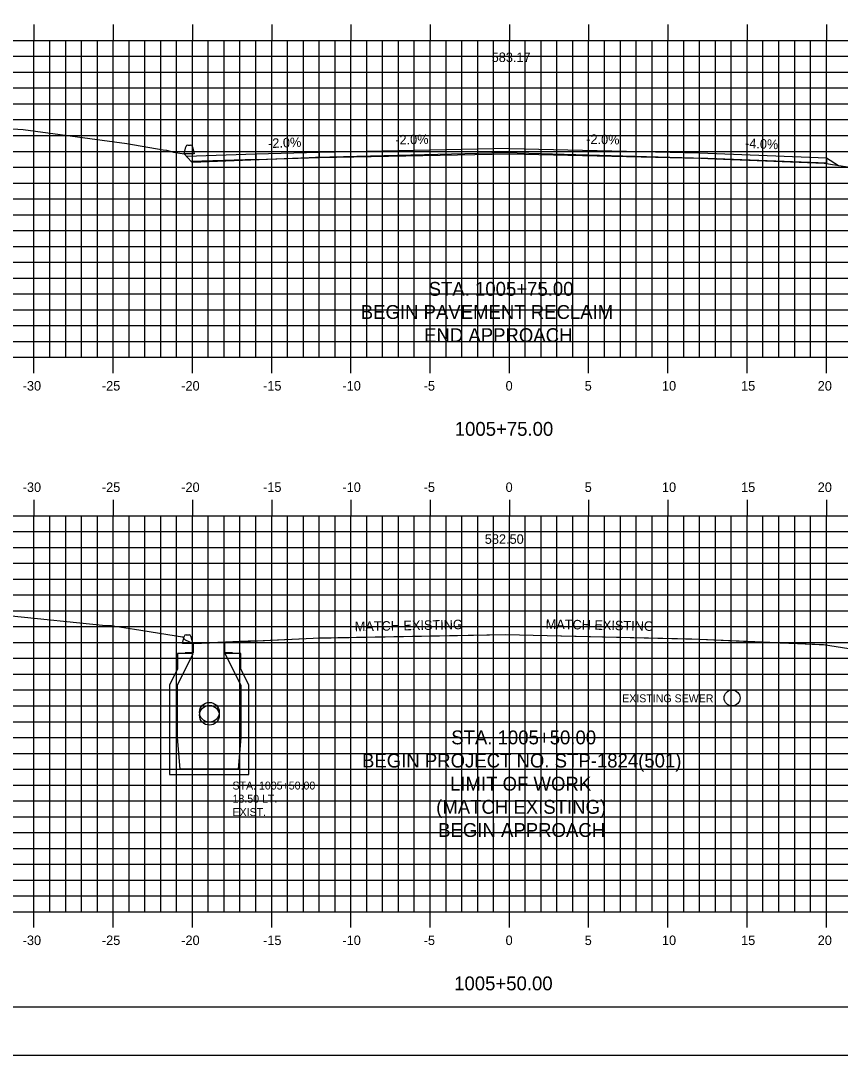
# Model space of a CAD drawing. Extents: x 1047919 to 1048089, y 779716 to 779826.
# Drawn here: x 1047971.1 to 1048022.8, y 779715.6 to 779781 of the extents above; entities that cross this region are included whole.
import ezdxf

# ---------------------------------------------------------------- set-up
doc = ezdxf.new("R2010")
doc.units = 0
for name, color, linetype in [('ANNOTATION', 7, 'Continuous'), ('BORDER', 7, 'Continuous'), ('D_Roadway_Berm', 7, 'Continuous'), ('D_Roadway_Centerline', 7, 'Continuous'), ('D_Roadway_Centerline_Text', 7, 'Continuous'), ('D_Roadway_Edge_Pavement', 7, 'Continuous'), ('D_Roadway_Edge_Shoulder', 7, 'Continuous'), ('D_Roadway_SlopeLines', 7, 'Continuous'), ('D_Text_Monospaced', 7, 'Continuous'), ('Existing Sewer', 7, 'Continuous'), ('H_V ANNOTATION', 7, 'Continuous'), ('MAJOR', 7, 'Continuous'), ('MINOR', 7, 'Continuous'), ('PLOT BOUNDARY', 7, 'Continuous'), ('S_Curb_Type_3', 7, 'Continuous'), ('S_Drainage_CB', 7, 'Continuous'), ('S_Drainage_Invert', 7, 'Continuous'), ('S_Roadway_Centerline', 7, 'Continuous')]:
    doc.layers.add(name, color=color, linetype=linetype)

msp = doc.modelspace()

# ---------------------------------------------------------------- linework, layer by layer
at = {"layer": 'BORDER'}
msp.add_lwpolyline([(1047926.957, 779718.706), (1048086.957, 779718.706), (1048086.957, 779823.706), (1047926.957, 779823.706)], close=True, dxfattribs=at)
at = {"layer": 'D_Roadway_Berm'}
msp.add_lwpolyline([(1047985.956, 779741.808), (1047985.956, 779741.808)], dxfattribs=at)
at = {"layer": 'D_Roadway_Centerline'}
for p, q in [((1047985.956, 779772.522), (1047981.585, 779772.39)), ((1047985.956, 779772.188), (1047981.871, 779772.066)), ((1048021.956, 779772.292), (1048022.713, 779771.821))]:
    msp.add_line(p, q, dxfattribs=at)
msp.add_lwpolyline([(1047981.959, 779741.638), (1047985.955, 779741.808), (1047985.956, 779741.808), (1047985.956, 779741.808), (1047989.569, 779741.982), (1047989.956, 779741.989), (1048001.705, 779742.215), (1048013.956, 779741.909), (1048016.956, 779741.781), (1048017.956, 779741.735)], dxfattribs=at)
at = {"layer": 'D_Roadway_Edge_Pavement'}
for q in [(1047989.956, 779772.642), (1048013.956, 779772.612)]:
    msp.add_line((1048001.956, 779772.876), q, dxfattribs=at)
msp.add_lwpolyline([(1048001.956, 779772.876), (1047989.956, 779772.642), (1047989.956, 779772.308), (1048001.956, 779772.542), (1048013.956, 779772.278), (1048013.956, 779772.612)], dxfattribs=at)
at = {"layer": 'D_Roadway_Edge_Shoulder'}
for p, q in [((1047989.956, 779772.642), (1047985.956, 779772.522)), ((1048013.956, 779772.612), (1048021.956, 779772.292))]:
    msp.add_line(p, q, dxfattribs=at)
for points in [[(1047985.956, 779772.522), (1047985.956, 779772.188), (1047989.956, 779772.308)], [(1048021.956, 779772.292), (1048021.956, 779771.958), (1048013.956, 779772.278)]]:
    msp.add_lwpolyline(points, dxfattribs=at)
at = {"layer": 'D_Roadway_SlopeLines'}
msp.add_line((1048017.956, 779741.735), (1048021.938, 779741.563), dxfattribs=at)
msp.add_lwpolyline([(1047985.956, 779741.808), (1047982.582, 779741.664)], dxfattribs=at)
at = {"layer": 'Existing Sewer'}
msp.add_circle((1048016.006, 779738.204), 0.5, dxfattribs=at)
at = {"layer": 'MAJOR'}
for p, q in [((1047971.956, 779780.708), (1047971.956, 779779.706)), ((1047976.956, 779780.708), (1047976.956, 779779.706)), ((1047981.956, 779780.708), (1047981.956, 779779.706)), ((1047986.956, 779780.708), (1047986.956, 779779.706)), ((1047991.956, 779780.708), (1047991.956, 779779.706)), ((1047996.956, 779780.708), (1047996.956, 779779.706)), ((1048001.956, 779780.708), (1048001.956, 779779.706)), ((1048006.956, 779780.708), (1048006.956, 779779.706)), ((1048011.956, 779780.708), (1048011.956, 779779.706)), ((1048016.956, 779780.708), (1048016.956, 779779.706)), ((1048021.956, 779780.708), (1048021.956, 779779.706)), ((1047931.956, 779779.706), (1048071.956, 779779.706)), ((1047931.956, 779779.706), (1048071.956, 779779.706)), ((1047971.956, 779759.706), (1047971.956, 779779.706)), ((1047976.956, 779759.706), (1047976.956, 779779.706)), ((1047981.956, 779759.706), (1047981.956, 779779.706)), ((1047986.956, 779759.706), (1047986.956, 779779.706)), ((1047991.956, 779759.706), (1047991.956, 779779.706)), ((1047996.956, 779759.706), (1047996.956, 779779.706)), ((1048001.956, 779759.706), (1048001.956, 779779.706)), ((1048006.956, 779759.706), (1048006.956, 779779.706)), ((1048011.956, 779759.706), (1048011.956, 779779.706)), ((1048016.956, 779759.706), (1048016.956, 779779.706)), ((1048021.956, 779759.706), (1048021.956, 779779.706)), ((1047931.956, 779774.706), (1048071.956, 779774.706)), ((1047931.956, 779769.706), (1048071.956, 779769.706)), ((1047931.956, 779764.706), (1048071.956, 779764.706)), ((1047931.956, 779759.706), (1048071.956, 779759.706)), ((1047931.956, 779759.706), (1048071.956, 779759.706)), ((1047971.956, 779758.704), (1047971.956, 779759.706)), ((1047976.956, 779758.704), (1047976.956, 779759.706)), ((1047981.956, 779758.704), (1047981.956, 779759.706)), ((1047986.956, 779758.704), (1047986.956, 779759.706)), ((1047991.956, 779758.704), (1047991.956, 779759.706)), ((1047996.956, 779758.704), (1047996.956, 779759.706)), ((1048001.956, 779758.704), (1048001.956, 779759.706)), ((1048006.956, 779758.704), (1048006.956, 779759.706)), ((1048011.956, 779758.704), (1048011.956, 779759.706)), ((1048016.956, 779758.704), (1048016.956, 779759.706)), ((1048021.956, 779758.704), (1048021.956, 779759.706)), ((1047971.956, 779750.708), (1047971.956, 779749.706)), ((1047976.956, 779750.708), (1047976.956, 779749.706)), ((1047981.956, 779750.708), (1047981.956, 779749.706)), ((1047986.956, 779750.708), (1047986.956, 779749.706)), ((1047991.956, 779750.708), (1047991.956, 779749.706)), ((1047996.956, 779750.708), (1047996.956, 779749.706)), ((1048001.956, 779750.708), (1048001.956, 779749.706)), ((1048006.956, 779750.708), (1048006.956, 779749.706)), ((1048011.956, 779750.708), (1048011.956, 779749.706)), ((1048016.956, 779750.708), (1048016.956, 779749.706)), ((1048021.956, 779750.708), (1048021.956, 779749.706)), ((1047931.956, 779749.706), (1048071.956, 779749.706)), ((1047931.956, 779749.706), (1048071.956, 779749.706)), ((1047971.956, 779724.706), (1047971.956, 779749.706)), ((1047976.956, 779724.706), (1047976.956, 779749.706)), ((1047981.956, 779724.706), (1047981.956, 779749.706)), ((1047986.956, 779724.706), (1047986.956, 779749.706)), ((1047991.956, 779724.706), (1047991.956, 779749.706)), ((1047996.956, 779724.706), (1047996.956, 779749.706)), ((1048001.956, 779724.706), (1048001.956, 779749.706)), ((1048006.956, 779724.706), (1048006.956, 779749.706)), ((1048011.956, 779724.706), (1048011.956, 779749.706)), ((1048016.956, 779724.706), (1048016.956, 779749.706)), ((1048021.956, 779724.706), (1048021.956, 779749.706)), ((1047931.956, 779744.706), (1048071.956, 779744.706)), ((1047931.956, 779739.706), (1048071.956, 779739.706)), ((1047931.956, 779734.706), (1048071.956, 779734.706)), ((1047931.956, 779729.706), (1048071.956, 779729.706)), ((1047931.956, 779724.706), (1048071.956, 779724.706)), ((1047931.956, 779724.706), (1048071.956, 779724.706)), ((1047971.956, 779723.704), (1047971.956, 779724.706)), ((1047976.956, 779723.704), (1047976.956, 779724.706)), ((1047981.956, 779723.704), (1047981.956, 779724.706)), ((1047986.956, 779723.704), (1047986.956, 779724.706)), ((1047991.956, 779723.704), (1047991.956, 779724.706)), ((1047996.956, 779723.704), (1047996.956, 779724.706)), ((1048001.956, 779723.704), (1048001.956, 779724.706)), ((1048006.956, 779723.704), (1048006.956, 779724.706)), ((1048011.956, 779723.704), (1048011.956, 779724.706)), ((1048016.956, 779723.704), (1048016.956, 779724.706)), ((1048021.956, 779723.704), (1048021.956, 779724.706))]:
    msp.add_line(p, q, dxfattribs=at)
at = {"layer": 'MINOR'}
for p, q in [((1047972.956, 779759.706), (1047972.956, 779779.706)), ((1047973.956, 779759.706), (1047973.956, 779779.706)), ((1047974.956, 779759.706), (1047974.956, 779779.706)), ((1047975.956, 779759.706), (1047975.956, 779779.706)), ((1047977.956, 779759.706), (1047977.956, 779779.706)), ((1047978.956, 779759.706), (1047978.956, 779779.706)), ((1047979.956, 779759.706), (1047979.956, 779779.706)), ((1047980.956, 779759.706), (1047980.956, 779779.706)), ((1047982.956, 779759.706), (1047982.956, 779779.706)), ((1047983.956, 779759.706), (1047983.956, 779779.706)), ((1047984.956, 779759.706), (1047984.956, 779779.706)), ((1047985.956, 779759.706), (1047985.956, 779779.706)), ((1047987.956, 779759.706), (1047987.956, 779779.706)), ((1047988.956, 779759.706), (1047988.956, 779779.706)), ((1047989.956, 779759.706), (1047989.956, 779779.706)), ((1047990.956, 779759.706), (1047990.956, 779779.706)), ((1047992.956, 779759.706), (1047992.956, 779779.706)), ((1047993.956, 779759.706), (1047993.956, 779779.706)), ((1047994.956, 779759.706), (1047994.956, 779779.706)), ((1047995.956, 779759.706), (1047995.956, 779779.706)), ((1047997.956, 779759.706), (1047997.956, 779779.706)), ((1047998.956, 779759.706), (1047998.956, 779779.706)), ((1047999.956, 779759.706), (1047999.956, 779779.706)), ((1048000.956, 779759.706), (1048000.956, 779779.706)), ((1048002.956, 779759.706), (1048002.956, 779779.706)), ((1048003.956, 779759.706), (1048003.956, 779779.706)), ((1048004.956, 779759.706), (1048004.956, 779779.706)), ((1048005.956, 779759.706), (1048005.956, 779779.706)), ((1048007.956, 779759.706), (1048007.956, 779779.706)), ((1048008.956, 779759.706), (1048008.956, 779779.706)), ((1048009.956, 779759.706), (1048009.956, 779779.706)), ((1048010.956, 779759.706), (1048010.956, 779779.706)), ((1048012.956, 779759.706), (1048012.956, 779779.706)), ((1048013.956, 779759.706), (1048013.956, 779779.706)), ((1048014.956, 779759.706), (1048014.956, 779779.706)), ((1048015.956, 779759.706), (1048015.956, 779779.706)), ((1048017.956, 779759.706), (1048017.956, 779779.706)), ((1048018.956, 779759.706), (1048018.956, 779779.706)), ((1048019.956, 779759.706), (1048019.956, 779779.706)), ((1048020.956, 779759.706), (1048020.956, 779779.706)), ((1047931.956, 779778.706), (1048071.956, 779778.706)), ((1047931.956, 779777.706), (1048071.956, 779777.706)), ((1047931.956, 779776.706), (1048071.956, 779776.706)), ((1047931.956, 779775.706), (1048071.956, 779775.706)), ((1047931.956, 779773.706), (1048071.956, 779773.706)), ((1047931.956, 779772.706), (1048071.956, 779772.706)), ((1047931.956, 779771.706), (1048071.956, 779771.706)), ((1047931.956, 779770.706), (1048071.956, 779770.706)), ((1047931.956, 779768.706), (1048071.956, 779768.706)), ((1047931.956, 779767.706), (1048071.956, 779767.706)), ((1047931.956, 779766.706), (1048071.956, 779766.706)), ((1047931.956, 779765.706), (1048071.956, 779765.706)), ((1047931.956, 779763.706), (1048071.956, 779763.706)), ((1047931.956, 779762.706), (1048071.956, 779762.706)), ((1047931.956, 779761.706), (1048071.956, 779761.706)), ((1047931.956, 779760.706), (1048071.956, 779760.706)), ((1047972.956, 779724.706), (1047972.956, 779749.706)), ((1047973.956, 779724.706), (1047973.956, 779749.706)), ((1047974.956, 779724.706), (1047974.956, 779749.706)), ((1047975.956, 779724.706), (1047975.956, 779749.706)), ((1047977.956, 779724.706), (1047977.956, 779749.706)), ((1047978.956, 779724.706), (1047978.956, 779749.706)), ((1047979.956, 779724.706), (1047979.956, 779749.706)), ((1047980.956, 779724.706), (1047980.956, 779749.706)), ((1047982.956, 779724.706), (1047982.956, 779749.706)), ((1047983.956, 779724.706), (1047983.956, 779749.706)), ((1047984.956, 779724.706), (1047984.956, 779749.706)), ((1047985.956, 779724.706), (1047985.956, 779749.706)), ((1047987.956, 779724.706), (1047987.956, 779749.706)), ((1047988.956, 779724.706), (1047988.956, 779749.706)), ((1047989.956, 779724.706), (1047989.956, 779749.706)), ((1047990.956, 779724.706), (1047990.956, 779749.706)), ((1047992.956, 779724.706), (1047992.956, 779749.706)), ((1047993.956, 779724.706), (1047993.956, 779749.706)), ((1047994.956, 779724.706), (1047994.956, 779749.706)), ((1047995.956, 779724.706), (1047995.956, 779749.706)), ((1047997.956, 779724.706), (1047997.956, 779749.706)), ((1047998.956, 779724.706), (1047998.956, 779749.706)), ((1047999.956, 779724.706), (1047999.956, 779749.706)), ((1048000.956, 779724.706), (1048000.956, 779749.706)), ((1048002.956, 779724.706), (1048002.956, 779749.706)), ((1048003.956, 779724.706), (1048003.956, 779749.706)), ((1048004.956, 779724.706), (1048004.956, 779749.706)), ((1048005.956, 779724.706), (1048005.956, 779749.706)), ((1048007.956, 779724.706), (1048007.956, 779749.706)), ((1048008.956, 779724.706), (1048008.956, 779749.706)), ((1048009.956, 779724.706), (1048009.956, 779749.706)), ((1048010.956, 779724.706), (1048010.956, 779749.706)), ((1048012.956, 779724.706), (1048012.956, 779749.706)), ((1048013.956, 779724.706), (1048013.956, 779749.706)), ((1048014.956, 779724.706), (1048014.956, 779749.706)), ((1048015.956, 779724.706), (1048015.956, 779749.706)), ((1048017.956, 779724.706), (1048017.956, 779749.706)), ((1048018.956, 779724.706), (1048018.956, 779749.706)), ((1048019.956, 779724.706), (1048019.956, 779749.706)), ((1048020.956, 779724.706), (1048020.956, 779749.706)), ((1047931.956, 779748.706), (1048071.956, 779748.706)), ((1047931.956, 779747.706), (1048071.956, 779747.706)), ((1047931.956, 779746.706), (1048071.956, 779746.706)), ((1047931.956, 779745.706), (1048071.956, 779745.706)), ((1047931.956, 779743.706), (1048071.956, 779743.706)), ((1047931.956, 779742.706), (1048071.956, 779742.706)), ((1047931.956, 779741.706), (1048071.956, 779741.706)), ((1047931.956, 779740.706), (1048071.956, 779740.706)), ((1047931.956, 779738.706), (1048071.956, 779738.706)), ((1047931.956, 779737.706), (1048071.956, 779737.706)), ((1047931.956, 779736.706), (1048071.956, 779736.706)), ((1047931.956, 779735.706), (1048071.956, 779735.706)), ((1047931.956, 779733.706), (1048071.956, 779733.706)), ((1047931.956, 779732.706), (1048071.956, 779732.706)), ((1047931.956, 779731.706), (1048071.956, 779731.706)), ((1047931.956, 779730.706), (1048071.956, 779730.706)), ((1047931.956, 779728.706), (1048071.956, 779728.706)), ((1047931.956, 779727.706), (1048071.956, 779727.706)), ((1047931.956, 779726.706), (1048071.956, 779726.706)), ((1047931.956, 779725.706), (1048071.956, 779725.706))]:
    msp.add_line(p, q, dxfattribs=at)
at = {"layer": 'PLOT BOUNDARY'}
msp.add_lwpolyline([(1047918.863, 779715.646), (1048088.863, 779715.646), (1048088.863, 779825.646), (1047918.863, 779825.646)], close=True, dxfattribs=at)
at = {"layer": 'S_Curb_Type_3'}
for points in [[(1047981.964, 779772.998), (1047982.066, 779772.553), (1047981.441, 779772.553), (1047981.544, 779772.998)], [(1047981.666, 779773.095), (1047981.842, 779773.095)], [(1047981.859, 779742.089), (1047981.962, 779741.644), (1047981.337, 779741.644), (1047981.44, 779742.089)], [(1047981.561, 779742.185), (1047981.738, 779742.185)]]:
    msp.add_lwpolyline(points, dxfattribs=at)
for centre, start, end in [((1047981.666, 779772.97), 90, 167.00538), ((1047981.842, 779772.97), 12.99462, 90), ((1047981.561, 779742.06), 90, 167.00538), ((1047981.738, 779742.06), 12.99462, 90)]:
    msp.add_arc(centre, 0.125, start, end, dxfattribs=at)
at = {"layer": 'S_Drainage_CB'}
for p, q in [((1047981.994, 779741.017), (1047981.01, 779741.017)), ((1047981.01, 779741.017), (1047981.01, 779740.032)), ((1047981.01, 779739.015), (1047981.994, 779741.017)), ((1047985.012, 779741.017), (1047983.995, 779741.017)), ((1047983.995, 779741.017), (1047985.012, 779739.015)), ((1047985.012, 779740.032), (1047985.012, 779741.017)), ((1047981.01, 779740.032), (1047980.517, 779739.015)), ((1047985.504, 779739.015), (1047985.012, 779740.032)), ((1047980.517, 779739.015), (1047980.517, 779733.372)), ((1047981.01, 779735.702), (1047981.01, 779739.015)), ((1047985.012, 779739.015), (1047985.012, 779735.702)), ((1047985.504, 779733.372), (1047985.504, 779739.015)), ((1047981.174, 779733.7), (1047981.01, 779735.702)), ((1047985.012, 779735.702), (1047984.848, 779733.7)), ((1047980.517, 779733.372), (1047985.504, 779733.372)), ((1047984.848, 779733.7), (1047981.174, 779733.7))]:
    msp.add_line(p, q, dxfattribs=at)
msp.add_lwpolyline([(1047984.487, 779741.058), (1047983.995, 779741.058), (1047983.995, 779741.682), (1047981.994, 779741.682), (1047981.994, 779741.058), (1047981.502, 779741.058)], dxfattribs=at)
at = {"layer": 'S_Drainage_Invert'}
for centre in [(1047983.026, 779737.299), (1047983.026, 779737.112)]:
    msp.add_circle(centre, 0.625, dxfattribs=at)
at = {"layer": 'S_Roadway_Centerline'}
for points in [[(1047968.298, 779774.278), (1047971.279, 779774.083), (1047977.81, 779773.203), (1047980.116, 779772.797), (1047980.316, 779772.79), (1047980.56, 779772.713), (1047980.764, 779772.663), (1047981.441, 779772.553), (1047981.891, 779772.043), (1047981.951, 779772.015), (1047981.951, 779772.015), (1047989.324, 779772.318), (1047989.716, 779772.338), (1047990.621, 779772.353), (1048001.7, 779772.633), (1048011.345, 779772.35), (1048013.574, 779772.299), (1048014.935, 779772.24), (1048021.824, 779771.961), (1048026.367, 779771.244)], [(1047931.956, 779743.453), (1047943.724, 779743.414), (1047949.493, 779743.51), (1047952.756, 779743.487), (1047963.854, 779743.339), (1047970.33, 779743.413), (1047976.489, 779742.784), (1047976.843, 779742.779), (1047976.934, 779742.755), (1047978.299, 779742.547), (1047981.332, 779742.056), (1047981.486, 779741.882), (1047982, 779741.643), (1047982.001, 779741.64), (1047985.614, 779741.789), (1047989.569, 779741.982), (1047998.68, 779742.138), (1048001.705, 779742.215), (1048004.348, 779742.138), (1048013.473, 779741.93), (1048019.033, 779741.688), (1048021.766, 779741.578), (1048030.574, 779740.189)]]:
    msp.add_lwpolyline(points, dxfattribs=at)

# ---------------------------------------------------------------- texts
at = {"layer": 'ANNOTATION'}
for s, height, rotation, p in [('-2.0%', 0.6, 2.29087, (1047986.74, 779772.908)), ('-2.0%', 0.6, 1.14576, (1047994.759, 779773.132)), ('-2.0%', 0.6, 358.85424, (1048006.799, 779773.179)), ('-4.0%', 0.6, 357.70939, (1048016.815, 779772.922)), ('MATCH EXISTING', 0.6, 1.14576, (1047992.201, 779742.411)), ('MATCH EXISTING', 0.6, 358.85424, (1048004.241, 779742.57)), ('1.9%', 0.01, 1.10334, (1047995.817, 779742.106)), ('2.4%', 0.01, 358.61233, (1048007.572, 779742.077))]:
    msp.add_text(s, height=height, rotation=rotation, dxfattribs=at).set_placement(p)
for s, p in [('STA. 1005+75.00', (1047996.86, 779763.588)), ('BEGIN PAVEMENT RECLAIM', (1047992.576, 779762.127)), ('END APPROACH', (1047996.572, 779760.666)), ('STA. 1005+50.00', (1047998.285, 779735.275)), ('BEGIN PROJECT NO. STP-1824(501)', (1047992.654, 779733.814)), ('LIMIT OF WORK', (1047998.21, 779732.353)), ('(MATCH EXISTING)', (1047997.333, 779730.891)), ('BEGIN APPROACH', (1047997.46, 779729.43))]:
    msp.add_text(s, height=0.875, dxfattribs=at).set_placement(p)
at = {"layer": 'D_Roadway_Centerline_Text'}
for s, p in [('583.17', (1048000.838, 779778.343)), ('582.50', (1048000.404, 779747.932))]:
    msp.add_text(s, height=0.6, dxfattribs=at).set_placement(p)
at = {"layer": 'D_Text_Monospaced'}
for s, height, p in [('EXISTING SEWER', 0.49998, (1048009.071, 779737.928)), ('STA. 1005+50.00', 0.49998, (1047984.484, 779732.423)), ('18.50 LT.', 0.5, (1047984.484, 779731.589)), ('EXIST. ', 0.5, (1047984.484, 779730.749))]:
    msp.add_text(s, height=height, dxfattribs=at).set_placement(p)
at = {"layer": 'H_V ANNOTATION'}
for s, height, p in [('-30', 0.6, (1047971.245, 779757.606)), ('-25', 0.6, (1047976.242, 779757.606)), ('-20', 0.6, (1047981.25, 779757.606)), ('-15', 0.6, (1047986.413, 779757.606)), ('-10', 0.6, (1047991.421, 779757.606)), ('-5', 0.6, (1047996.547, 779757.606)), ('0', 0.6, (1048001.715, 779757.606)), ('5', 0.6, (1048006.707, 779757.606)), ('10', 0.6, (1048011.582, 779757.606)), ('15', 0.6, (1048016.574, 779757.606)), ('20', 0.6, (1048021.41, 779757.606)), ('1005+75.00', 0.875, (1047998.507, 779754.749)), ('-30', 0.6, (1047971.245, 779751.206)), ('-25', 0.6, (1047976.242, 779751.206)), ('-20', 0.6, (1047981.25, 779751.206)), ('-15', 0.6, (1047986.413, 779751.206)), ('-10', 0.6, (1047991.421, 779751.206)), ('-5', 0.6, (1047996.547, 779751.206)), ('0', 0.6, (1048001.715, 779751.206)), ('5', 0.6, (1048006.707, 779751.206)), ('10', 0.6, (1048011.582, 779751.206)), ('15', 0.6, (1048016.574, 779751.206)), ('20', 0.6, (1048021.41, 779751.206)), ('-30', 0.6, (1047971.245, 779722.606)), ('-25', 0.6, (1047976.242, 779722.606)), ('-20', 0.6, (1047981.25, 779722.606)), ('-15', 0.6, (1047986.413, 779722.606)), ('-10', 0.6, (1047991.421, 779722.606)), ('-5', 0.6, (1047996.547, 779722.606)), ('0', 0.6, (1048001.715, 779722.606)), ('5', 0.6, (1048006.707, 779722.606)), ('10', 0.6, (1048011.582, 779722.606)), ('15', 0.6, (1048016.574, 779722.606)), ('20', 0.6, (1048021.41, 779722.606)), ('1005+50.00', 0.875, (1047998.468, 779719.749))]:
    msp.add_text(s, height=height, dxfattribs=at).set_placement(p)
at = {"layer": 'S_Roadway_Centerline'}
for s, p in [('C', (1048001.695, 779772.633)), ('L', (1048001.7, 779772.626))]:
    msp.add_text(s, height=0.0146, dxfattribs=at).set_placement(p)

doc.saveas('drawing.dxf')
